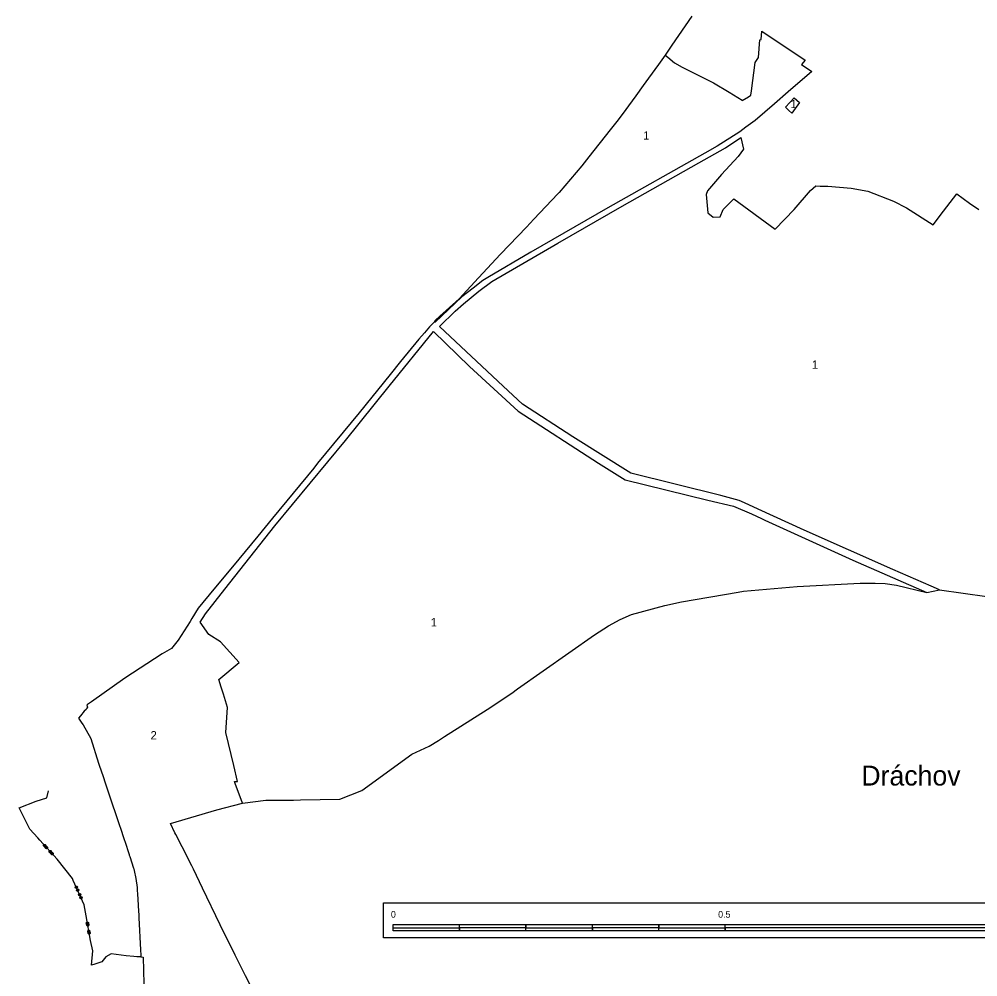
# Model space of a CAD drawing. Extents: x -738939 to -735528, y -1140462 to -1136895.
# Drawn here: x -738906 to -737462, y -1139715 to -1138274 of the extents above; entities that cross this region are included whole.
import ezdxf

# ---------------------------------------------------------------- set-up
doc = ezdxf.new("R2010")
doc.units = 0
for name, color, linetype in [('GR_MER', 7, 'Continuous'), ('HRA_KU', 7, 'Continuous'), ('KU_OST', 7, 'Continuous'), ('NERES_SET', 7, 'Continuous'), ('OVNE_PRE', 7, 'Continuous'), ('OZN', 7, 'Continuous')]:
    doc.layers.add(name, color=color, linetype=linetype)

msp = doc.modelspace()

# ---------------------------------------------------------------- linework, layer by layer
at = {"layer": 'GR_MER'}
for points in [[(-736745.8, -1139603.8), (-736745.8, -1139656.4), (-738357.1, -1139656.4), (-738357.1, -1139603.8), (-736745.8, -1139603.8)], [(-738342.6, -1139641.3), (-738342.6, -1139636.3), (-738242.6, -1139636.3)], [(-738142.6, -1139641.3), (-738142.6, -1139636.3), (-738042.6, -1139636.3)], [(-737942.6, -1139641.3), (-737942.6, -1139636.3), (-737842.6, -1139636.3)], [(-738142.6, -1139646.3), (-738242.6, -1139646.3), (-738242.6, -1139641.3)], [(-737942.6, -1139646.3), (-738042.6, -1139646.3), (-738042.6, -1139641.3)], [(-737342.6, -1139646.3), (-737842.6, -1139646.3), (-737842.6, -1139641.3)]]:
    msp.add_lwpolyline(points, dxfattribs=at)
for points in [[(-738142.6, -1139641.3), (-738242.6, -1139641.3), (-738242.6, -1139636.3), (-738142.6, -1139636.3)], [(-737942.6, -1139641.3), (-738042.6, -1139641.3), (-738042.6, -1139636.3), (-737942.6, -1139636.3)], [(-737342.6, -1139641.3), (-737842.6, -1139641.3), (-737842.6, -1139636.3), (-737342.6, -1139636.3)], [(-738242.6, -1139646.3), (-738342.6, -1139646.3), (-738342.6, -1139641.3), (-738242.6, -1139641.3)], [(-738042.6, -1139646.3), (-738142.6, -1139646.3), (-738142.6, -1139641.3), (-738042.6, -1139641.3)], [(-737842.6, -1139646.3), (-737942.6, -1139646.3), (-737942.6, -1139641.3), (-737842.6, -1139641.3)]]:
    msp.add_lwpolyline(points, close=True, dxfattribs=at)
at = {"layer": 'HRA_KU'}
for points in [[(-738722.2, -1139685.3), (-738724.5, -1139685.2), (-738728.2, -1139685.1), (-738733.1, -1139684.9), (-738744.4, -1139683.5), (-738767.1, -1139680.7), (-738775.3, -1139685.4), (-738781, -1139692.6), (-738791.7, -1139696.1), (-738796.7, -1139697.8), (-738794.6, -1139676.3), (-738798.3, -1139660.7), (-738804.7, -1139623.6), (-738807.6, -1139606.7), (-738824.1, -1139570.3), (-738825.4, -1139567.4), (-738848.5, -1139538.3), (-738874.6, -1139509.4), (-738877.6, -1139506.1), (-738889.6, -1139492.9), (-738905.5, -1139461.1), (-738880, -1139451), (-738863.7, -1139446.1), (-738861.2, -1139435.4)], [(-738868.8, -1139518.2), (-738868.7, -1139516.8), (-738867.7, -1139515.9), (-738866.4, -1139516), (-738865.5, -1139517), (-738865.6, -1139518.3), (-738866.6, -1139519.2), (-738867.9, -1139519.2), (-738868.8, -1139518.2), (-738868.6, -1139518.1), (-738867.8, -1139519), (-738867.2, -1139519.1), (-738868.5, -1139517.6), (-738868.5, -1139517), (-738866.6, -1139519.1), (-738866.3, -1139518.8), (-738868.2, -1139516.7), (-738867.9, -1139516.5), (-738866, -1139518.6), (-738865.7, -1139518.3), (-738867.6, -1139516.2), (-738867, -1139516.2), (-738865.7, -1139517.7), (-738865.7, -1139517.2), (-738866.5, -1139516.3)], [(-738866.2, -1139521.1), (-738866.1, -1139519.7), (-738865.1, -1139518.8), (-738863.8, -1139518.9), (-738862.9, -1139519.9), (-738862.9, -1139521.2), (-738863.9, -1139522.2), (-738865.3, -1139522.1), (-738866.2, -1139521.1), (-738865.9, -1139521.1), (-738865.1, -1139521.9), (-738864.6, -1139522), (-738865.9, -1139520.5), (-738865.9, -1139519.9), (-738864, -1139522), (-738863.7, -1139521.7), (-738865.6, -1139519.7), (-738865.3, -1139519.4), (-738863.4, -1139521.5), (-738863.1, -1139521.2), (-738865, -1139519.1), (-738864.4, -1139519.2), (-738863.1, -1139520.6), (-738863, -1139520.1), (-738863.9, -1139519.2)], [(-738860.4, -1139527.5), (-738860.4, -1139526.1), (-738859.4, -1139525.2), (-738858, -1139525.3), (-738857.1, -1139526.3), (-738857.2, -1139527.6), (-738858.2, -1139528.5), (-738859.5, -1139528.5), (-738860.4, -1139527.5), (-738860.3, -1139527.4), (-738859.5, -1139528.2), (-738858.9, -1139528.3), (-738860.2, -1139526.8), (-738860.2, -1139526.2), (-738858.3, -1139528.3), (-738858, -1139528), (-738859.9, -1139526), (-738859.6, -1139525.7), (-738857.7, -1139527.8), (-738857.4, -1139527.5), (-738859.3, -1139525.4), (-738858.7, -1139525.5), (-738857.4, -1139526.9), (-738857.4, -1139526.4), (-738858.2, -1139525.5)], [(-738857.8, -1139530.4), (-738857.7, -1139529), (-738856.7, -1139528.1), (-738855.4, -1139528.2), (-738854.5, -1139529.2), (-738854.6, -1139530.5), (-738855.6, -1139531.4), (-738856.9, -1139531.4), (-738857.8, -1139530.4), (-738857.6, -1139530.3), (-738856.8, -1139531.2), (-738856.3, -1139531.2), (-738857.6, -1139529.7), (-738857.6, -1139529.1), (-738855.7, -1139531.2), (-738855.4, -1139531), (-738857.3, -1139528.9), (-738857, -1139528.6), (-738855.1, -1139530.7), (-738854.8, -1139530.4), (-738856.7, -1139528.3), (-738856.1, -1139528.4), (-738854.8, -1139529.9), (-738854.7, -1139529.3), (-738855.6, -1139528.4)], [(-738821.3, -1139580.4), (-738820.8, -1139579.1), (-738819.6, -1139578.6), (-738818.3, -1139579), (-738817.7, -1139580.3), (-738818.2, -1139581.5), (-738819.4, -1139582.1), (-738820.7, -1139581.6), (-738821.3, -1139580.4), (-738821, -1139580.4), (-738820.5, -1139581.5), (-738820, -1139581.7), (-738820.8, -1139579.9), (-738820.6, -1139579.4), (-738819.5, -1139581.9), (-738819.1, -1139581.7), (-738820.2, -1139579.2), (-738819.9, -1139579), (-738818.7, -1139581.6), (-738818.4, -1139581.4), (-738819.5, -1139578.9), (-738819, -1139579.1), (-738818.2, -1139580.9), (-738818, -1139580.4), (-738818.5, -1139579.3)], [(-738819.2, -1139584.9), (-738818.7, -1139583.7), (-738817.5, -1139583.1), (-738816.2, -1139583.6), (-738815.7, -1139584.8), (-738816.1, -1139586.1), (-738817.4, -1139586.6), (-738818.6, -1139586.2), (-738819.2, -1139584.9), (-738818.9, -1139585), (-738818.4, -1139586.1), (-738817.9, -1139586.3), (-738818.7, -1139584.5), (-738818.5, -1139583.9), (-738817.4, -1139586.5), (-738817, -1139586.3), (-738818.2, -1139583.8), (-738817.8, -1139583.6), (-738816.7, -1139586.2), (-738816.3, -1139586), (-738817.5, -1139583.4), (-738816.9, -1139583.6), (-738816.1, -1139585.5), (-738815.9, -1139584.9), (-738816.4, -1139583.8)], [(-738816.1, -1139591.8), (-738815.6, -1139590.5), (-738814.4, -1139589.9), (-738813.1, -1139590.4), (-738812.6, -1139591.6), (-738813.1, -1139592.9), (-738814.3, -1139593.5), (-738815.5, -1139593), (-738816.1, -1139591.8), (-738815.9, -1139591.7), (-738815.4, -1139592.8), (-738814.9, -1139593), (-738815.7, -1139591.2), (-738815.5, -1139590.7), (-738814.3, -1139593.2), (-738814, -1139593), (-738815.1, -1139590.5), (-738814.8, -1139590.3), (-738813.6, -1139592.9), (-738813.3, -1139592.7), (-738814.4, -1139590.2), (-738813.9, -1139590.4), (-738813.1, -1139592.2), (-738812.9, -1139591.7), (-738813.3, -1139590.6)], [(-738814, -1139596.3), (-738813.6, -1139595.1), (-738812.3, -1139594.5), (-738811.1, -1139595), (-738810.5, -1139596.2), (-738811, -1139597.5), (-738812.2, -1139598), (-738813.5, -1139597.6), (-738814, -1139596.3), (-738813.8, -1139596.3), (-738813.3, -1139597.4), (-738812.8, -1139597.6), (-738813.6, -1139595.8), (-738813.4, -1139595.2), (-738812.3, -1139597.8), (-738811.9, -1139597.6), (-738813.1, -1139595.1), (-738812.7, -1139594.9), (-738811.5, -1139597.4), (-738811.2, -1139597.3), (-738812.3, -1139594.7), (-738811.8, -1139594.9), (-738811, -1139596.8), (-738810.8, -1139596.2), (-738811.3, -1139595.1)], [(-738804.5, -1139634.1), (-738803.7, -1139633), (-738802.4, -1139632.8), (-738801.3, -1139633.6), (-738801.1, -1139634.9), (-738801.9, -1139636), (-738803.2, -1139636.2), (-738804.3, -1139635.4), (-738804.5, -1139634.1), (-738804.3, -1139634.2), (-738804.1, -1139635.4), (-738803.6, -1139635.7), (-738804, -1139633.8), (-738803.6, -1139633.3), (-738803.2, -1139636.1), (-738802.8, -1139636), (-738803.2, -1139633.2), (-738802.8, -1139633.2), (-738802.4, -1139635.9), (-738802, -1139635.9), (-738802.4, -1139633.1), (-738802, -1139633.4), (-738801.7, -1139635.4), (-738801.3, -1139634.9), (-738801.5, -1139633.8)], [(-738804.1, -1139636.7), (-738803.3, -1139635.6), (-738802, -1139635.3), (-738800.9, -1139636.1), (-738800.6, -1139637.4), (-738801.4, -1139638.5), (-738802.8, -1139638.8), (-738803.8, -1139638), (-738804.1, -1139636.7), (-738803.9, -1139636.8), (-738803.6, -1139638), (-738803.2, -1139638.3), (-738803.5, -1139636.3), (-738803.2, -1139635.9), (-738802.7, -1139638.6), (-738802.3, -1139638.5), (-738802.8, -1139635.8), (-738802.4, -1139635.7), (-738801.9, -1139638.5), (-738801.5, -1139638.4), (-738802, -1139635.6), (-738801.6, -1139636), (-738801.2, -1139637.9), (-738800.9, -1139637.5), (-738801.1, -1139636.3)], [(-738802.4, -1139646.4), (-738801.6, -1139645.3), (-738800.3, -1139645.1), (-738799.2, -1139645.9), (-738799, -1139647.2), (-738799.7, -1139648.3), (-738801.1, -1139648.5), (-738802.2, -1139647.8), (-738802.4, -1139646.4), (-738802.2, -1139646.4), (-738802, -1139647.6), (-738801.5, -1139648), (-738801.9, -1139646), (-738801.5, -1139645.5), (-738801.1, -1139648.3), (-738800.7, -1139648.2), (-738801.1, -1139645.5), (-738800.8, -1139645.4), (-738800.3, -1139648.2), (-738799.9, -1139648.1), (-738800.4, -1139645.3), (-738799.9, -1139645.7), (-738799.6, -1139647.6), (-738799.2, -1139647.2), (-738799.4, -1139646)], [(-738802, -1139649), (-738801.2, -1139647.9), (-738799.9, -1139647.7), (-738798.8, -1139648.4), (-738798.5, -1139649.8), (-738799.3, -1139650.9), (-738800.6, -1139651.1), (-738801.7, -1139650.3), (-738802, -1139649), (-738801.8, -1139649), (-738801.6, -1139650.2), (-738801.1, -1139650.5), (-738801.4, -1139648.5), (-738801.1, -1139648.1), (-738800.6, -1139650.8), (-738800.2, -1139650.8), (-738800.7, -1139648), (-738800.3, -1139647.9), (-738799.8, -1139650.7), (-738799.5, -1139650.6), (-738799.9, -1139647.9), (-738799.5, -1139648.2), (-738799.1, -1139650.2), (-738798.8, -1139649.7), (-738799, -1139648.5)]]:
    msp.add_lwpolyline(points, dxfattribs=at)
at = {"layer": 'NERES_SET'}
for points in [[(-737933, -1138328), (-737929.1, -1138331.3), (-737918.9, -1138339.8), (-737907.5, -1138346.4), (-737860.5, -1138369.6), (-737836.7, -1138383.9), (-737817.1, -1138395.8), (-737817, -1138396.4), (-737807.8, -1138390.9), (-737804, -1138388.5), (-737803.3, -1138381.7), (-737797.6, -1138339), (-737792.5, -1138331.8), (-737790.5, -1138304.9), (-737788.4, -1138304.8), (-737787.6, -1138292), (-737722.5, -1138335.7), (-737728.1, -1138342.1), (-737712.2, -1138352.7), (-737747.7, -1138383.1), (-737768.3, -1138401.2), (-737797.8, -1138426.4), (-737811.8, -1138436.4), (-737820.7, -1138443.4), (-737854.8, -1138464.9)], [(-737742.3, -1138415.5), (-737746.8, -1138411.4), (-737752.1, -1138406.5), (-737738.7, -1138392.3), (-737730.8, -1138399.3), (-737742.3, -1138415.5)], [(-737520, -1139132.8), (-737532.5, -1139127.2), (-737590.5, -1139102.3), (-737724, -1139042.9), (-737793, -1139011.2), (-737813.9, -1139002), (-737821.9, -1138998.2), (-737849.4, -1138991), (-737984.7, -1138957.5), (-738072.1, -1138902.5), (-738147.8, -1138853.2), (-738177, -1138826.1), (-738272.6, -1138736.7), (-738249.2, -1138713.5), (-738236.8, -1138702.2), (-738213.7, -1138683.1), (-738194.1, -1138669), (-738094.6, -1138611.3), (-737997.6, -1138555.6), (-737882.2, -1138490.3), (-737842.4, -1138467.4), (-737819, -1138452)], [(-737819, -1138452), (-737815.4, -1138469.7), (-737823.1, -1138480.9), (-737848.1, -1138507.8), (-737869.2, -1138532.1), (-737871.4, -1138537.8), (-737868.7, -1138565.4), (-737860.7, -1138572), (-737850.5, -1138571.5), (-737845.8, -1138560.3), (-737829.6, -1138544.3), (-737767.6, -1138589.8), (-737738.7, -1138560.6), (-737714.3, -1138531.9), (-737706.1, -1138524.6), (-737699.7, -1138525.2), (-737688.2, -1138525.4), (-737653.3, -1138528.5), (-737627.8, -1138533), (-737589.5, -1138548.1), (-737569.6, -1138557.9), (-737529.8, -1138583.5), (-737514, -1138563.1), (-737494.3, -1138536.8), (-737475, -1138550.7), (-737460.7, -1138560.5)], [(-737854.8, -1138464.9), (-737873.5, -1138475.4), (-738019.4, -1138558.1), (-738135.1, -1138624.4), (-738200.2, -1138662.6), (-738207.7, -1138667.5), (-738222, -1138678.7), (-738239, -1138692), (-738279.4, -1138730.2), (-738280.8, -1138730.2)], [(-738569.4, -1139453.8), (-738578.7, -1139428.5), (-738579.7, -1139425.7), (-738581.4, -1139421.5), (-738577.1, -1139421.3), (-738582.6, -1139397.1), (-738594.6, -1139347.5), (-738591.8, -1139309.7), (-738598, -1139290), (-738601.5, -1139279.5), (-738605.2, -1139267.6), (-738574.4, -1139242.2), (-738602.3, -1139211.2), (-738620.1, -1139200), (-738633, -1139181.7), (-738624.8, -1139168.9), (-738596.1, -1139132), (-738520.7, -1139036.3), (-738414.3, -1138908.2), (-738348.4, -1138826.2), (-738281.6, -1138744), (-738227.7, -1138796.7), (-738154.6, -1138863.9), (-738033.5, -1138942.2), (-737993.4, -1138967.5), (-737869, -1138997.8), (-737830.1, -1139006.9), (-737803.3, -1139018.6), (-737788.3, -1139025.4), (-737783, -1139027.9), (-737650.8, -1139088), (-737539, -1139136.7)]]:
    msp.add_lwpolyline(points, dxfattribs=at)
at = {"layer": 'OVNE_PRE'}
msp.add_line((-737539, -1139136.7), (-737520, -1139132.8), dxfattribs=at)
for points in [[(-737893.2, -1138269.5), (-737922.9, -1138313.2), (-737933, -1138328)], [(-737933, -1138328), (-737943, -1138342.4), (-737958.2, -1138362.8), (-737966.2, -1138373.8), (-737977.3, -1138389.2), (-737982.7, -1138396.7), (-737997.7, -1138417.4), (-738005.9, -1138428), (-738015.8, -1138440.6), (-738047.8, -1138481), (-738058.5, -1138494.6), (-738092.9, -1138534.9), (-738094.9, -1138537.1), (-738130.7, -1138575.2), (-738141.8, -1138586.8), (-738181.1, -1138627.9), (-738214, -1138663.2), (-738243.3, -1138694.9), (-738272.2, -1138721), (-738279.2, -1138727.4), (-738280.8, -1138730.2)], [(-738280.8, -1138730.2), (-738281.2, -1138730.5), (-738287, -1138736.1), (-738287.8, -1138736.8), (-738295.5, -1138745.9), (-738303.7, -1138755.6), (-738331.6, -1138789.3), (-738347, -1138808.6), (-738393.9, -1138866.4), (-738456.4, -1138942.4), (-738462.2, -1138949.7), (-738524.2, -1139025.2), (-738546.1, -1139052.1), (-738584.6, -1139098.3), (-738612.6, -1139131.9), (-738635.9, -1139160.5), (-738645.5, -1139175.8), (-738647.9, -1139180.5), (-738666.2, -1139208.6), (-738676.3, -1139221.3), (-738690.2, -1139229.3), (-738746.5, -1139265.6), (-738796.7, -1139301.3), (-738802.6, -1139305.6), (-738803.6, -1139306.3), (-738802.8, -1139309.2), (-738803.8, -1139311.1), (-738804.9, -1139313.2), (-738807.5, -1139315.7), (-738813.3, -1139322.5), (-738816.4, -1139326.1)], [(-737520, -1139132.8), (-737449.1, -1139142.7), (-737392.9, -1139149.3), (-737297.3, -1139161.5), (-737292.1, -1139160.6), (-737161.1, -1139178), (-737152.3, -1139179.2), (-737145.7, -1139180.2), (-737095.9, -1139186.6), (-737089.3, -1139186.4), (-737085.2, -1139183), (-737084.5, -1139168.8), (-737086.4, -1139124.2), (-737090.8, -1139075.7), (-737093.5, -1139061.9)], [(-738569.4, -1139453.8), (-738534.3, -1139449.6), (-738492.7, -1139449.6), (-738482, -1139448.9), (-738422.7, -1139447.9), (-738389.9, -1139434.9), (-738314.4, -1139380.4), (-738288.3, -1139367.9), (-738274.5, -1139359.4), (-738265.1, -1139353.4), (-738201.2, -1139313.1), (-738164.1, -1139288.3), (-738155.2, -1139281.8), (-738039.3, -1139200.4), (-738018.5, -1139186.8), (-738000.9, -1139177.5), (-737983.9, -1139170), (-737933.7, -1139156.5), (-737908.4, -1139151), (-737823.4, -1139136.3), (-737815.2, -1139134.9), (-737734.5, -1139128), (-737639.4, -1139122.8), (-737616.8, -1139122.6), (-737602, -1139123.3), (-737584.7, -1139125.9), (-737539, -1139136.7)], [(-738816.4, -1139326.1), (-738813.4, -1139330.5), (-738811.1, -1139333.3), (-738809.3, -1139335.8), (-738797.6, -1139356.8), (-738786, -1139393.8), (-738781.2, -1139408.2), (-738780.3, -1139411), (-738775.2, -1139426.1), (-738771.5, -1139437), (-738754.3, -1139487.4), (-738753.9, -1139488.8), (-738753.4, -1139490.1), (-738747.4, -1139508.8), (-738747, -1139510.2), (-738746.6, -1139511.3), (-738740.1, -1139531), (-738739.8, -1139532.1), (-738739.4, -1139533.1), (-738739, -1139534.4), (-738733.3, -1139551.6), (-738733, -1139553), (-738732.6, -1139555.1), (-738729.8, -1139567.2), (-738728.1, -1139580.7), (-738728, -1139582.1), (-738727.8, -1139583.5), (-738727.3, -1139592.5), (-738727.1, -1139596.8), (-738727, -1139598.5), (-738726.8, -1139600.5), (-738726.6, -1139605.7), (-738726.5, -1139607.7), (-738726.4, -1139609), (-738725.6, -1139622.5), (-738725.4, -1139625.3), (-738725.4, -1139626.6), (-738722.8, -1139674.9), (-738722.4, -1139682.7), (-738722.2, -1139685.3)], [(-738556, -1139731.5), (-738564.6, -1139714), (-738580.2, -1139682.6), (-738602.8, -1139637.1), (-738629.4, -1139581.7), (-738643.1, -1139553.2), (-738645.8, -1139548), (-738660.4, -1139519.4), (-738669.8, -1139501.1), (-738671.2, -1139498.5), (-738677.6, -1139484.5), (-738607.9, -1139463.9), (-738569.4, -1139453.8)], [(-738722.2, -1139685.3), (-738718.7, -1139685.5), (-738717.7, -1139725.7)]]:
    msp.add_lwpolyline(points, dxfattribs=at)

# ---------------------------------------------------------------- texts
at = {"layer": 'GR_MER'}
for s, p in [('0', (-738345.9, -1139626.3)), ('0.5', (-737853.4, -1139626.3))]:
    msp.add_text(s, height=10, dxfattribs=at).set_placement(p)
at = {"layer": 'KU_OST'}
msp.add_text('Dráchov', height=30, dxfattribs=at).set_placement((-737637.8, -1139427.4))
at = {"layer": 'OZN'}
for s, p in [('1', (-737744.4, -1138407.9)), ('1', (-737966.2, -1138455.3)), ('1', (-737712.1, -1138800.1)), ('1', (-738286, -1139187.9)), ('2', (-738707.7, -1139358))]:
    msp.add_text(s, height=12.5, dxfattribs=at).set_placement(p)

doc.saveas('drawing.dxf')
